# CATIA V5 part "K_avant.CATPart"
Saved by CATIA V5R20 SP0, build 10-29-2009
Part number: avant
Bounding box of the stored display mesh (mm): x -100 to 100, y -258.752 to 41.667, z -5 to 37.619
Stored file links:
  G:\Khaled_CFAO_2011\SIL\SIL_GR2\ahabrial\ahabrial\Khaled\CAD_ThinkMOTION\K_avant.CATPart
  G:\Données\Ecole\IFMA\2A\Thinkmotion2\Etape18\trotinette.CATProduct
  G:\Khaled_CFAO_2011\SIL\SIL_GR2\ahabrial\ahabrial\Etape18\skl_avant.CATPart
  G:\Khaled_CFAO_2011\SIL\SIL_GR2\ahabrial\ahabrial\Khaled\CAD_ThinkMOTION\K_skl_bati.CATPart
  G:\Khaled_CFAO_2011\SIL\SIL_GR2\ahabrial\ahabrial\Etape18\guidon_haut.CATPart
  G:\Khaled_CFAO_2011\SIL\SIL_GR2\ahabrial\ahabrial\Khaled\CAD_ThinkMOTION\K_arriere.CATPart
  G:\Khaled_CFAO_2011\SIL\SIL_GR2\ahabrial\ahabrial\Khaled\CAD_ThinkMOTION\K_guidon.CATPart
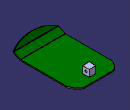
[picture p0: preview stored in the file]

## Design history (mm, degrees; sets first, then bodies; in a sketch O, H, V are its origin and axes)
Parameters
  Longueur_planche_avant = 250 mm
  Largeur_planche_avant = 200 mm
  epaisseur_planche_avant = 5 mm
  `Longueur_coté_pivot_avant` = 30 mm
  Diametre_pivot_avant = 10 mm
External parameters (linked from other documents)
  `External.Longueur-arriere` = 740 mm
Set1
  Plane1 "Plan_avant_guidon": linked copy from another document
  Point1: linked copy from another document
  Line1: linked copy from another document
  Line2 "axe_guidon_avant": linked copy from another document
  Point2: linked copy from another document
  Point3: linked copy from another document
  Line3: linked copy from another document
Body1 (main body)
  Sketch1 on Plane1, origin (0, 0, 0), H (1, 0, 0), V (0, -1, 0)
    line L1 (-100, 208.3333) -> (100, 208.3333)
    line L2 (100, 208.3333) -> (100, -41.6667)
    line L3 (100, -41.6667) -> (-100, -41.6667)
    line L4 (-100, -41.6667) -> (-100, 208.3333)
    reference projected point E1 (0, 0) from Point1
    reference projected point E2 (0, 0) from Point1
    distance E1 L4 = 100 {= Largeur_planche_avant /2}
    length L1 = 200 {= Largeur_planche_avant}
    length L2 = 250 {= Longueur_planche_avant}
    distance E2 L3 = 41.6667 {= Longueur_planche_avant /6}
    horizontal: L1 H, L3 H
    vertical: L2 V, L4 V
  Pad1: profile Sketch1, direction (0, 0, -1), length 5 {= epaisseur_planche_avant}
  Sketch2 on start face of Pad1, origin (0, 0, 0), H (1, 0, 0), V (0, 1, 0)
    spline S1 through (-100, 0) (-70, 40) (0, 50) (70, 40) (100, 0)
    line L1 (100, 0) -> (100, 70)
    point P1 (100, 0)
    line L2 (100, 70) -> (-100, 70)
    line L3 (-100, 70) -> (-100, 0)
    point P4 (-100, 0)
    point P5 (-100, 0)
    point P6 (0, 50)
    point P7 (100, 0)
    coincidence: P5 H, P6 V, P7 H, P7 P1, P5 P4
    vertical: L1 V, L3 V
    horizontal: L2 H
  Pocket1: profile Sketch2, direction (0, 0, -1), length 5
  Sketch3 on Plane1, origin (0, 0, 0), H (1, 0, 0), V (0, -1, 0)
    line L1 (-15, 15) -> (15, 15)
    line L2 (15, 15) -> (15, -15)
    line L3 (15, -15) -> (-15, -15)
    line L4 (-15, -15) -> (-15, 15)
    reference projected point E1 (0, 0) from Point3
    reference projected point E2 (0, 0) from Point3
    length L1 = 30 {= `Longueur_coté_pivot_avant`}
    length L2 = 30 {= `Longueur_coté_pivot_avant`}
    distance E1 L1 = 15 {= `Longueur_coté_pivot_avant` /2}
    distance E2 L4 = 15 {= `Longueur_coté_pivot_avant` /2}
    horizontal: L1 H, L3 H
    vertical: L2 V, L4 V
  Pad2: profile Sketch3, direction (0, 0, 1), length 30 {= `Longueur_coté_pivot_avant`}
  Sketch4 on face of Pad2 from Sketch3.L2, origin (15, 5.4887, 20.4887), H (0, 1, 0), V (0, 0, 1)
    point P1 (-5.4887, -5.4887)
    reference projected line E1 (9.5113, 9.5113) -> (-20.4887, 9.5113) from edge [end face of Pad2 | face of Pad2 from Sketch3.L2]
    reference projected line E2 (-20.4887, -20.4887) -> (-20.4887, 9.5113) from edge [face of Pad2 from Sketch3.L2 | face of Pad2 from Sketch3.L1]
    distance E1 P1 = 15 {= `Longueur_coté_pivot_avant` /2}
    distance P1 E2 = 15 {= `Longueur_coté_pivot_avant` /2}
  Hole1: placed by Sketch4, at (15, 0, 15) direction (-1, 0, 0), diameter 10 {= Diametre_pivot_avant}, through (limit type 6)
  Plane2 "Plan_construction_avant": type Angle, RefPlane face of Pad1 from Sketch1.L1, Direction edge [face of Pad1 from Sketch1.L1 | end face of Pad1], Angle -65
  Sketch5 on Plane2, origin (0, -39.1248, -83.9033), H (-1, 0, 0), V (0, -0.9063, 0.4226)
    line L1 (-100, 223.701) -> (100, 223.701)
    line L2 (100, 223.701) -> (100, 186.701)
    line L3 (100, 186.701) -> (-100, 186.701)
    line L4 (-100, 186.701) -> (-100, 223.701)
    point P3 (100, 186.701)
    reference projected line E1 (-100, 186.701) -> (100, 186.701) from edge [face of Pad1 from Sketch1.L1 | end face of Pad1]
    reference projected point E2 (100, 186.701) from vertex [face of Pad1 from Sketch1.L1 | end face of Pad1 | face of Pad1 from Sketch1.L4]
    length L3 = 200 {= Largeur_planche_avant}
    length L2 = 37 {= `External.Longueur-arriere` /20}
    horizontal: L1 H, L3 H
    vertical: L2 V, L4 V
    coincidence: E1 L3, P3 E2
  Pad3: profile Sketch5, direction (0, 0.4226, 0.9063), length 5 {= epaisseur_planche_avant}
  Plane3 "Plan_construction_avant_arrondi2": type Angle, RefPlane face of Pad3 from Sketch5.L1, Direction edge [start face of Pad3 | face of Pad3 from Sketch5.L1], Angle -120
  Sketch6 on Plane3, origin (0, -157.2973, -110.1407), H (1, 0, 0), V (0, -0.5736, 0.8192)
    line L1 (0, 147.4423) -> (100, 147.4423)
    point P1 (0, 147.4423)
    point P2 (100, 147.4423)
    reference projected line E1 (-100, 147.4423) -> (100, 147.4423) from edge [start face of Pad3 | face of Pad3 from Sketch5.L1]
    spline S1 through (100, 147.4423) (88.944, 155.0673) (29.698, 174.8173) (0, 176.8803)
    reference projected point E2 (100, 147.4423) from vertex [face of Pad3 from Sketch5.L4 | start face of Pad3 | face of Pad3 from Sketch5.L1]
    reference projected line E3 (0, 303.0863) -> (0, 0) from Line3
    axis line L2 (0, 200) -> (0, 140)
    point P5 (-100, 147.4423)
    point P6 (0, 147.4423)
    line L3 (0, 147.4423) -> (-100, 147.4423)
    spline S2 through (-100, 147.4423) (-88.944, 155.0673) (-29.698, 174.8173) (0, 176.8803)
    point P7 (100, 147.4423)
    point P8 (0, 176.8803)
    point P9 (88.944, 155.0673)
    point P10 (29.698, 174.8173)
    point P11 (0, 176.8803)
    point P12 (-100, 147.4423)
    point P13 (-29.698, 174.8173)
    point P14 (-88.944, 155.0673)
    length L1 = 100 {= Largeur_planche_avant /2}
    horizontal: L1 H
    coincidence: L1 E1, P7 P2, P8 V, P7 E2, P8 E3, P8 L2, P5 P12
    vertical: L2 V
    symmetry: P2 P5 L2, P1 P6 L2, L1 L3 L2, S1 S2 L2, P8 P11 L2, P7 P12 L2, P10 P13 L2, P9 P14 L2
  Pad4: profile Sketch6, direction (0, 0.8192, 0.5736), length 5 {= epaisseur_planche_avant}
  Fillet1: radius 5, on edge [end face of Pad3 | start face of Pad1]; edge [end face of Pad3 | end face of Pad4]
  Fillet2: radius 5, on edge [start face of Pad3 | start face of Pad4]; edge [start face of Pad3 | end face of Pad1]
